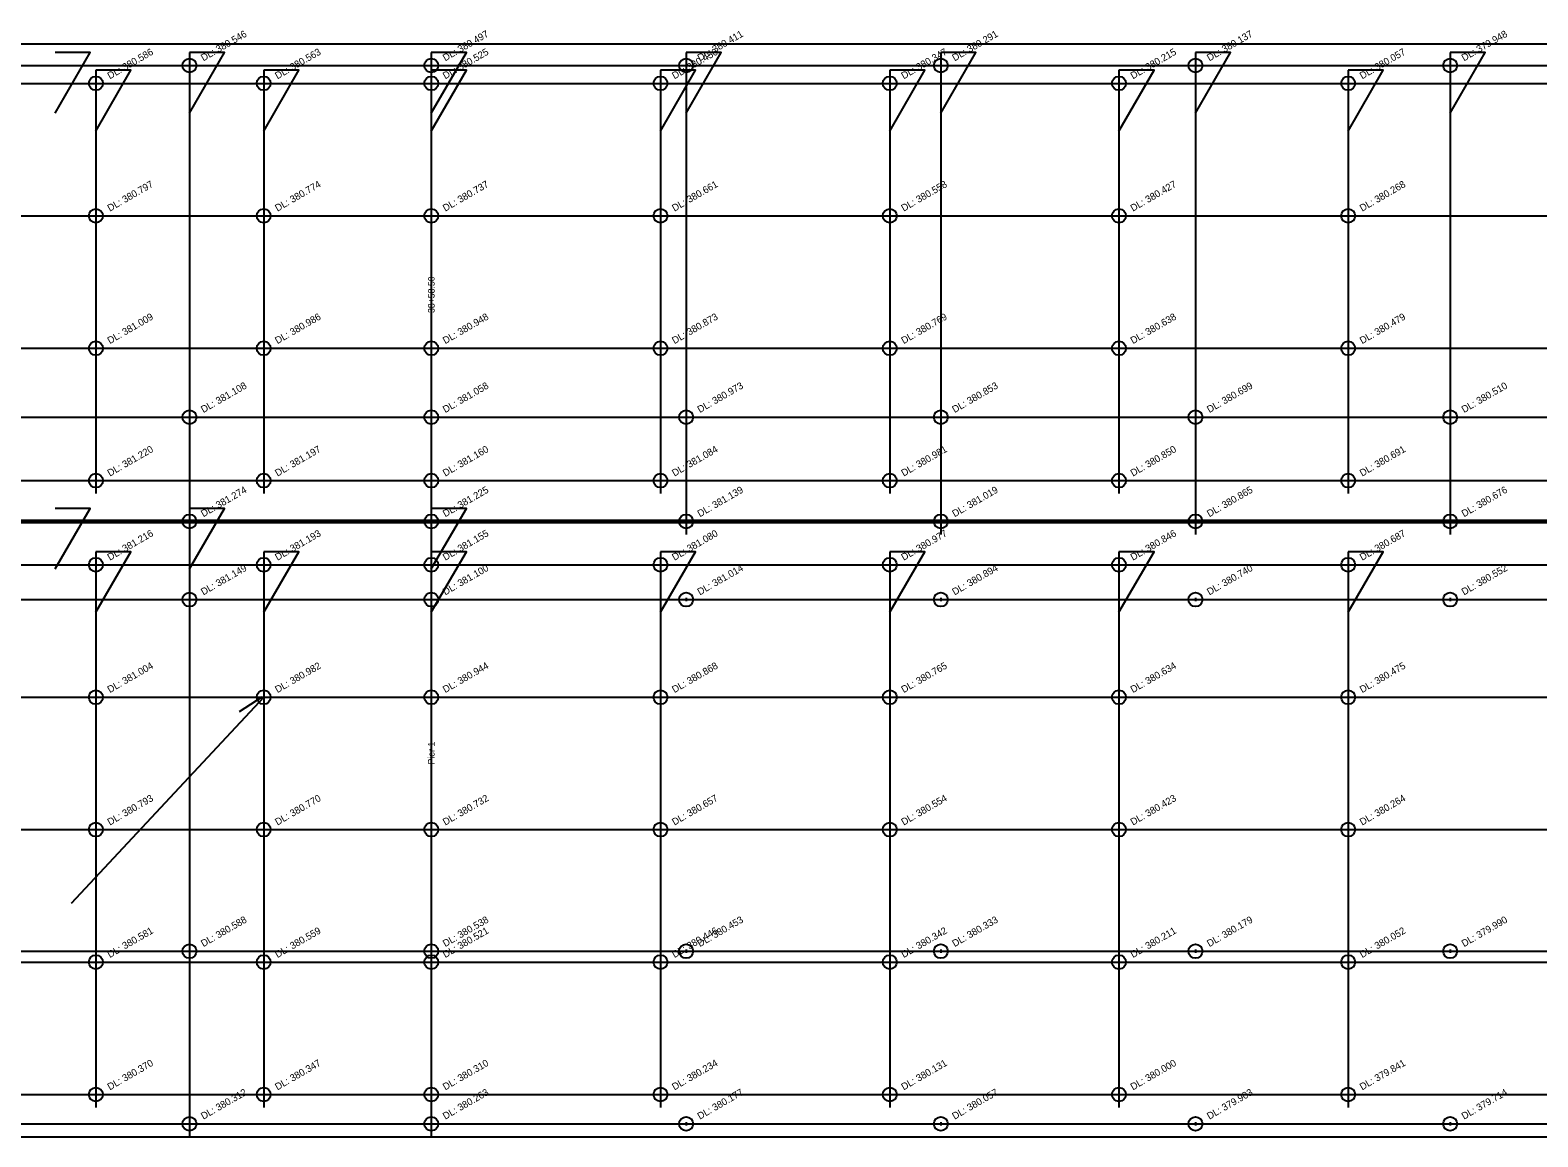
# Model space of a CAD drawing. Extents: x 100440 to 101111, y 50226 to 50315.
# Drawn here: x 100658.7 to 100774.5, y 50225.9 to 50310.9 of the extents above; entities that cross this region are included whole.
import ezdxf

# ---------------------------------------------------------------- set-up
doc = ezdxf.new("R2010")
doc.units = 0
for name, color, linetype in [('Level 1', 7, 'Continuous'), ('Level 10', 7, 'Continuous'), ('Level 21', 7, 'Continuous'), ('Level 23', 7, 'Continuous')]:
    doc.layers.add(name, color=color, linetype=linetype)

msp = doc.modelspace()

# ---------------------------------------------------------------- linework, layer by layer
at = {"layer": 'Level 1'}
for p, q in [((100559.5, 50306.77), (101034.5, 50306.77)), ((100559.5, 50296.6), (101034.5, 50296.6)), ((100689.5, 50288.14), (100689.5, 50258.14)), ((100689.5, 50288.14), (100689.5, 50258.14)), ((100559.5, 50286.43), (101034.5, 50286.43)), ((100559.5, 50276.27), (101034.5, 50276.27)), ((100559.5, 50269.81), (101034.5, 50269.81)), ((100559.5, 50259.64), (101034.5, 50259.64)), ((100559.5, 50249.48), (101034.5, 50249.48)), ((100559.5, 50239.31), (101034.5, 50239.31)), ((100559.5, 50229.14), (101034.5, 50229.14))]:
    msp.add_line(p, q, dxfattribs=at)
at = {"layer": 'Level 10'}
for p, q in [((100689.5, 50273.27), (100689.5, 50273.02)), ((100709.06, 50273.27), (100709.06, 50273.02)), ((100728.62, 50273.27), (100728.62, 50273.02)), ((100748.17, 50273.27), (100748.17, 50273.02)), ((100767.73, 50273.27), (100767.73, 50273.02)), ((100689.5, 50267.27), (100689.5, 50267.02)), ((100709.06, 50267.27), (100709.06, 50267.02)), ((100728.62, 50267.27), (100728.62, 50267.02)), ((100748.17, 50267.27), (100748.17, 50267.02)), ((100767.73, 50267.27), (100767.73, 50267.02)), ((100689.5, 50240.27), (100689.5, 50240.02)), ((100709.06, 50240.27), (100709.06, 50240.02)), ((100728.62, 50240.27), (100728.62, 50240.02)), ((100748.17, 50240.27), (100748.17, 50240.02)), ((100767.73, 50240.27), (100767.73, 50240.02)), ((100689.5, 50227.02), (100689.5, 50226.77)), ((100709.06, 50227.02), (100709.06, 50226.77)), ((100728.62, 50227.02), (100728.62, 50226.77)), ((100748.17, 50227.02), (100748.17, 50226.77)), ((100767.73, 50227.02), (100767.73, 50226.77))]:
    msp.add_line(p, q, dxfattribs=at)
for points in [[(100660.62, 50304.49), (100663.3, 50309.14), (100660.62, 50309.14)], [(100670.93, 50309.14), (100670.93, 50272.14)], [(100670.93, 50304.49), (100673.62, 50309.14), (100670.93, 50309.14)], [(100689.5, 50309.14), (100689.5, 50272.14)], [(100689.5, 50304.49), (100692.19, 50309.14), (100689.5, 50309.14)], [(100689.5, 50309.14), (100689.5, 50272.14)], [(100689.5, 50304.49), (100692.19, 50309.14), (100689.5, 50309.14)], [(100709.06, 50309.14), (100709.06, 50272.14)], [(100709.06, 50304.49), (100711.75, 50309.14), (100709.06, 50309.14)], [(100728.62, 50309.14), (100728.62, 50272.14)], [(100728.62, 50304.49), (100731.3, 50309.14), (100728.62, 50309.14)], [(100748.17, 50309.14), (100748.17, 50272.14)], [(100748.17, 50304.49), (100750.86, 50309.14), (100748.17, 50309.14)], [(100767.73, 50309.14), (100767.73, 50272.14)], [(100767.73, 50304.49), (100770.41, 50309.14), (100767.73, 50309.14)], [(100663.75, 50307.77), (100663.75, 50275.27)], [(100663.75, 50303.11), (100666.44, 50307.77), (100663.75, 50307.77)], [(100676.63, 50307.77), (100676.63, 50275.27)], [(100676.63, 50303.11), (100679.32, 50307.77), (100676.63, 50307.77)], [(100689.5, 50307.77), (100689.5, 50275.27)], [(100689.5, 50303.11), (100692.19, 50307.77), (100689.5, 50307.77)], [(100707.1, 50307.77), (100707.1, 50275.27)], [(100707.1, 50303.11), (100709.79, 50307.77), (100707.1, 50307.77)], [(100724.7, 50307.77), (100724.7, 50275.27)], [(100724.7, 50303.11), (100727.39, 50307.77), (100724.7, 50307.77)], [(100742.3, 50307.77), (100742.3, 50275.27)], [(100742.3, 50303.11), (100744.99, 50307.77), (100742.3, 50307.77)], [(100759.9, 50307.77), (100759.9, 50275.27)], [(100759.9, 50303.11), (100762.59, 50307.77), (100759.9, 50307.77)], [(100660.62, 50269.49), (100663.3, 50274.14), (100660.62, 50274.14)], [(100670.93, 50274.14), (100670.93, 50225.89)], [(100670.93, 50269.49), (100673.62, 50274.14), (100670.93, 50274.14)], [(100689.5, 50274.14), (100689.5, 50225.89)], [(100689.5, 50269.49), (100692.19, 50274.14), (100689.5, 50274.14)], [(100663.75, 50270.81), (100663.75, 50228.14)], [(100663.75, 50266.16), (100666.44, 50270.81), (100663.75, 50270.81)], [(100676.63, 50270.81), (100676.63, 50228.14)], [(100676.63, 50266.16), (100679.32, 50270.81), (100676.63, 50270.81)], [(100689.5, 50270.81), (100689.5, 50228.14)], [(100689.5, 50266.16), (100692.19, 50270.81), (100689.5, 50270.81)], [(100707.1, 50270.81), (100707.1, 50228.14)], [(100707.1, 50266.16), (100709.79, 50270.81), (100707.1, 50270.81)], [(100724.7, 50270.81), (100724.7, 50228.14)], [(100724.7, 50266.16), (100727.39, 50270.81), (100724.7, 50270.81)], [(100742.3, 50270.81), (100742.3, 50228.14)], [(100742.3, 50266.16), (100744.99, 50270.81), (100742.3, 50270.81)], [(100759.9, 50270.81), (100759.9, 50228.14)], [(100759.9, 50266.16), (100762.59, 50270.81), (100759.9, 50270.81)]]:
    msp.add_lwpolyline(points, dxfattribs=at)
for centre in [(100670.93, 50308.14), (100689.5, 50308.14), (100689.5, 50308.14), (100709.06, 50308.14), (100728.62, 50308.14), (100748.17, 50308.14), (100767.73, 50308.14), (100663.75, 50306.77), (100676.63, 50306.77), (100689.5, 50306.77), (100707.1, 50306.77), (100724.7, 50306.77), (100742.3, 50306.77), (100759.9, 50306.77), (100663.75, 50296.6), (100676.63, 50296.6), (100689.5, 50296.6), (100707.1, 50296.6), (100724.7, 50296.6), (100742.3, 50296.6), (100759.9, 50296.6), (100663.75, 50286.43), (100676.63, 50286.43), (100689.5, 50286.43), (100707.1, 50286.43), (100724.7, 50286.43), (100742.3, 50286.43), (100759.9, 50286.43), (100670.93, 50281.14), (100689.5, 50281.14), (100689.5, 50281.14), (100709.06, 50281.14), (100728.62, 50281.14), (100748.17, 50281.14), (100767.73, 50281.14), (100663.75, 50276.27), (100676.63, 50276.27), (100689.5, 50276.27), (100707.1, 50276.27), (100724.7, 50276.27), (100742.3, 50276.27), (100759.9, 50276.27), (100670.93, 50273.14), (100670.93, 50273.14), (100689.5, 50273.14), (100689.5, 50273.14), (100689.5, 50273.14), (100689.5, 50273.14), (100709.06, 50273.14), (100709.06, 50273.14), (100728.62, 50273.14), (100728.62, 50273.14), (100748.17, 50273.14), (100748.17, 50273.14), (100767.73, 50273.14), (100767.73, 50273.14), (100663.75, 50269.81), (100676.63, 50269.81), (100689.5, 50269.81), (100707.1, 50269.81), (100724.7, 50269.81), (100742.3, 50269.81), (100759.9, 50269.81), (100670.93, 50267.14), (100689.5, 50267.14), (100689.5, 50267.14), (100709.06, 50267.14), (100728.62, 50267.14), (100748.17, 50267.14), (100767.73, 50267.14), (100663.75, 50259.64), (100676.63, 50259.64), (100689.5, 50259.64), (100707.1, 50259.64), (100724.7, 50259.64), (100742.3, 50259.64), (100759.9, 50259.64), (100663.75, 50249.48), (100676.63, 50249.48), (100689.5, 50249.48), (100707.1, 50249.48), (100724.7, 50249.48), (100742.3, 50249.48), (100759.9, 50249.48), (100670.93, 50240.14), (100689.5, 50240.14), (100689.5, 50240.14), (100709.06, 50240.14), (100728.62, 50240.14), (100748.17, 50240.14), (100767.73, 50240.14), (100663.75, 50239.31), (100676.63, 50239.31), (100689.5, 50239.31), (100707.1, 50239.31), (100724.7, 50239.31), (100742.3, 50239.31), (100759.9, 50239.31), (100663.75, 50229.14), (100676.63, 50229.14), (100689.5, 50229.14), (100707.1, 50229.14), (100724.7, 50229.14), (100742.3, 50229.14), (100759.9, 50229.14), (100670.93, 50226.89), (100689.5, 50226.89), (100689.5, 50226.89), (100709.06, 50226.89), (100728.62, 50226.89), (100748.17, 50226.89), (100767.73, 50226.89)]:
    msp.add_circle(centre, 0.537, dxfattribs=at)
at = {"layer": 'Level 23'}
for p, q in [((100439.55, 50309.81), (101111.48, 50309.81)), ((100439.55, 50308.14), (101111.48, 50308.14)), ((100689.5, 50288.14), (100689.5, 50258.14)), ((100689.5, 50288.14), (100689.5, 50258.14)), ((100439.55, 50281.14), (101111.48, 50281.14)), ((100439.55, 50273.23), (101111.48, 50273.23)), ((100439.55, 50273.14), (101111.48, 50273.14)), ((100448.2, 50273.14), (101107.51, 50273.14)), ((100448.2, 50273.06), (101107.51, 50273.06)), ((100448.2, 50267.14), (101107.51, 50267.14)), ((100676.63, 50259.64), (100661.84, 50243.81)), ((100676.5, 50259.64), (100674.75, 50258.51)), ((100448.2, 50240.14), (101107.51, 50240.14)), ((100448.2, 50226.89), (101107.51, 50226.89)), ((100448.2, 50225.89), (101107.51, 50225.89))]:
    msp.add_line(p, q, dxfattribs=at)

# ---------------------------------------------------------------- texts
at = {"layer": 'Level 10'}
for s, p in [('DL: 380.546', (100672, 50308.45)), ('DL: 380.497', (100690.57, 50308.45)), ('DL: 380.497', (100690.57, 50308.45)), ('DL: 380.411', (100710.12, 50308.45)), ('DL: 380.291', (100729.68, 50308.45)), ('DL: 380.137', (100749.24, 50308.45)), ('DL: 379.948', (100768.79, 50308.45)), ('DL: 380.586', (100664.82, 50307.07)), ('DL: 380.563', (100677.69, 50307.07)), ('DL: 380.525', (100690.57, 50307.07)), ('DL: 380.450', (100708.17, 50307.07)), ('DL: 380.347', (100725.77, 50307.07)), ('DL: 380.215', (100743.37, 50307.07)), ('DL: 380.057', (100760.97, 50307.07)), ('DL: 380.797', (100664.82, 50296.91)), ('DL: 380.774', (100677.69, 50296.91)), ('DL: 380.737', (100690.57, 50296.91)), ('DL: 380.661', (100708.17, 50296.91)), ('DL: 380.558', (100725.77, 50296.91)), ('DL: 380.427', (100743.37, 50296.91)), ('DL: 380.268', (100760.97, 50296.91)), ('DL: 381.009', (100664.82, 50286.74)), ('DL: 380.986', (100677.69, 50286.74)), ('DL: 380.948', (100690.57, 50286.74)), ('DL: 380.873', (100708.17, 50286.74)), ('DL: 380.769', (100725.77, 50286.74)), ('DL: 380.638', (100743.37, 50286.74)), ('DL: 380.479', (100760.97, 50286.74)), ('DL: 381.108', (100672, 50281.45)), ('DL: 381.058', (100690.57, 50281.45)), ('DL: 381.058', (100690.57, 50281.45)), ('DL: 380.973', (100710.12, 50281.45)), ('DL: 380.853', (100729.68, 50281.45)), ('DL: 380.699', (100749.24, 50281.45)), ('DL: 380.510', (100768.79, 50281.45)), ('DL: 381.220', (100664.82, 50276.57)), ('DL: 381.197', (100677.69, 50276.57)), ('DL: 381.160', (100690.57, 50276.57)), ('DL: 381.084', (100708.17, 50276.57)), ('DL: 380.981', (100725.77, 50276.57)), ('DL: 380.850', (100743.37, 50276.57)), ('DL: 380.691', (100760.97, 50276.57)), ('DL: 381.274', (100672, 50273.45)), ('DL: 381.274', (100672, 50273.45)), ('DL: 381.225', (100690.57, 50273.45)), ('DL: 381.225', (100690.57, 50273.45)), ('DL: 381.225', (100690.57, 50273.45)), ('DL: 381.225', (100690.57, 50273.45)), ('DL: 381.139', (100710.12, 50273.45)), ('DL: 381.139', (100710.12, 50273.45)), ('DL: 381.019', (100729.68, 50273.45)), ('DL: 381.019', (100729.68, 50273.45)), ('DL: 380.865', (100749.24, 50273.45)), ('DL: 380.865', (100749.24, 50273.45)), ('DL: 380.676', (100768.79, 50273.45)), ('DL: 380.676', (100768.79, 50273.45)), ('DL: 381.216', (100664.82, 50270.11)), ('DL: 381.193', (100677.69, 50270.11)), ('DL: 381.155', (100690.57, 50270.11)), ('DL: 381.080', (100708.17, 50270.11)), ('DL: 380.977', (100725.77, 50270.11)), ('DL: 380.846', (100743.37, 50270.11)), ('DL: 380.687', (100760.97, 50270.11)), ('DL: 381.149', (100672, 50267.45)), ('DL: 381.100', (100690.57, 50267.45)), ('DL: 381.100', (100690.57, 50267.45)), ('DL: 381.014', (100710.12, 50267.45)), ('DL: 380.894', (100729.68, 50267.45)), ('DL: 380.740', (100749.24, 50267.45)), ('DL: 380.552', (100768.79, 50267.45)), ('DL: 381.004', (100664.82, 50259.95)), ('DL: 380.982', (100677.69, 50259.95)), ('DL: 380.944', (100690.57, 50259.95)), ('DL: 380.868', (100708.17, 50259.95)), ('DL: 380.765', (100725.77, 50259.95)), ('DL: 380.634', (100743.37, 50259.95)), ('DL: 380.475', (100760.97, 50259.95)), ('DL: 380.793', (100664.82, 50249.78)), ('DL: 380.770', (100677.69, 50249.78)), ('DL: 380.732', (100690.57, 50249.78)), ('DL: 380.657', (100708.17, 50249.78)), ('DL: 380.554', (100725.77, 50249.78)), ('DL: 380.423', (100743.37, 50249.78)), ('DL: 380.264', (100760.97, 50249.78)), ('DL: 380.588', (100672, 50240.45)), ('DL: 380.538', (100690.57, 50240.45)), ('DL: 380.538', (100690.57, 50240.45)), ('DL: 380.453', (100710.12, 50240.45)), ('DL: 380.333', (100729.68, 50240.45)), ('DL: 380.179', (100749.24, 50240.45)), ('DL: 379.990', (100768.79, 50240.45)), ('DL: 380.581', (100664.82, 50239.61)), ('DL: 380.559', (100677.69, 50239.61)), ('DL: 380.521', (100690.57, 50239.61)), ('DL: 380.446', (100708.17, 50239.61)), ('DL: 380.342', (100725.77, 50239.61)), ('DL: 380.211', (100743.37, 50239.61)), ('DL: 380.052', (100760.97, 50239.61)), ('DL: 380.370', (100664.82, 50229.45)), ('DL: 380.347', (100677.69, 50229.45)), ('DL: 380.310', (100690.57, 50229.45)), ('DL: 380.234', (100708.17, 50229.45)), ('DL: 380.131', (100725.77, 50229.45)), ('DL: 380.000', (100743.37, 50229.45)), ('DL: 379.841', (100760.97, 50229.45)), ('DL: 380.312', (100672, 50227.2)), ('DL: 380.263', (100690.57, 50227.2)), ('DL: 380.263', (100690.57, 50227.2)), ('DL: 380.177', (100710.12, 50227.2)), ('DL: 380.057', (100729.68, 50227.2)), ('DL: 379.903', (100749.24, 50227.2)), ('DL: 379.714', (100768.79, 50227.2))]:
    msp.add_text(s, height=0.5373, rotation=30, dxfattribs=at).set_placement(p)
at = {"layer": 'Level 21'}
for s, p in [('38+58.50', (100689.75, 50289.14)), ('38+58.50', (100689.75, 50289.14)), ('Pier 1', (100689.75, 50254.48)), ('Pier 1', (100689.75, 50254.48))]:
    msp.add_text(s, height=0.5, rotation=90, dxfattribs=at).set_placement(p)

doc.saveas('drawing.dxf')
